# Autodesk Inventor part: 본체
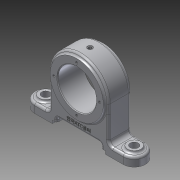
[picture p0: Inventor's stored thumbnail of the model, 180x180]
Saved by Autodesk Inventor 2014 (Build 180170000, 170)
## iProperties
Created: 2019-05
Part Number: 본체
Material: Aluminum 6061
Document SubType Name: Modeling
Designer: kh
Density: 2.71 g/cm^3
Appearance: Aluminum - Flat
Mass: 456.566 g
Surface Area: 322 cm^2
Volume: 168.474 cm^3
Author: kh
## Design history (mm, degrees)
sketch "Sketch1"
  geometry: L1 (-60, 0)-(60, 0); L2 (-60, 15)-(60, 15); L3 (60, -15)-(-60, -15); A1 r 15 centre (-60, 0) between (-60, 15) and (-60, -15); A2 r 15 centre (60, 0) between (60, -15) and (60, 15); 2 further points
  constraints: 8 end point, 4 point on circle, 4 tangent, 2 centre point, 1 coincident, 1 horizontal, 1 midpoint, 1 parallel
  dimensions: "d0" = 120 distance of L1.start L1.end; "d1" = 15 radius of A2
extrude "Extrusion1" new body sketch "Sketch1" distance "d2" = 12; taper "d3" = 0 deg
sketch "Sketch2"
  geometry: L1 (120, 0)-(0, 0) reference; L2 (120, 0)-(120, 12) reference; L3 (0, 12)-(120, 12) reference; L4 (0, 0)-(0, 12) reference; L5 (0, 0)-(0, 0) reference; L6 (0, 0)-(0, 12) reference; L7 (0, 12)-(0, 12) reference; L8 (0, 0)-(0, 12) reference; L9 (120, 0)-(120, 0) reference; L10 (120, 0)-(120, 12) reference; L11 (120, 12)-(120, 12) reference; L12 (120, 0)-(120, 12) reference; L13 (-15, 0)-(-15, 12) reference; L14 (135, 0)-(135, 12) reference; L15 (24, 4)-(96, 4); L16 (96, 4)-(96, 0); L17 (96, 0)-(24, 0); L18 (24, 0)-(24, 4); 2 further points
  constraints: 8 end point, 2 midpoint, 2 parallel, 1 horizontal, 1 perpendicular
  dimensions: "d4" = 72 distance of L16.end L17.end; "d5" = 4 distance of L15.end L16.end
extrude "Extrusion2" cut sketch "Sketch2" stored distance "d6" = 12; taper "d7" = 0 deg
sketch "Sketch3"
  geometry: L1 (96, -8)-(96, -12) reference; L2 (120, -12)-(96, -12) reference; L3 (120, -12)-(120, 0) reference; L4 (0, 0)-(120, 0) reference; L5 (0, -12)-(0, 0) reference; L6 (24, -12)-(0, -12) reference; L7 (24, -12)-(24, -8) reference; L8 (24, -8)-(96, -8) reference; L9 (60, -12)-(60, -8); L10 (30, -2)-(90, -2); L11 (90, -2)-(90, -8); L12 (90, -8)-(30, -8); L13 (30, -8)-(30, -2); L14 (24, -8)-(96, -8) reference; 1 further point
  constraints: 10 end point, 3 midpoint, 2 parallel, 1 horizontal, 1 perpendicular
  dimensions: "d8" = 60 distance of L11.end L12.end; "d9" = 6 distance of L10.end L11.end
extrude "Extrusion3" cut sketch "Sketch3" stored distance "d10" = 12; taper "d11" = 0 deg
sketch "Sketch4"
  geometry: L1 (-15, 0)-(15, 0) reference; L2 (-15, 0)-(-15, 12) reference; L3 (15, 12)-(-15, 12) reference; L4 (15, 0)-(15, 12) reference; L5 (-18, 60)-(-18, 96); L6 (-18, 96)-(18, 96); L7 (18, 96)-(18, 60); L8 (18, 60)-(-18, 60); L9 (-18, 86)-(18, 86); 3 further points
  constraints: 10 end point, 3 parallel, 2 midpoint, 2 perpendicular, 2 point on line, 1 vertical alignment
  dimensions: "d12" = 72 diameter of L6 L8; "d13" = 60 vertical distance of L5.start L1.start; "d14" = 52 diameter of L9 L8; "d15" = 36 distance of L5.end L6.end
revolve "Revolution1" sketch "Sketch4" stored, may be unused: angle "d16" = 90 deg
sketch "Sketch5"
  geometry: L1 (-30, 4)-(-30, 10) reference; L2 (-30, 10)-(30, 10) reference; L3 (30, 10)-(30, 4) reference; L4 (30, 4)-(36, 4) reference; L5 (36, 4)-(36, 0) reference; L6 (60, 0)-(36, 0) reference; L7 (60, 0)-(60, 12) reference; L8 (-60, 12)-(60, 12) reference; L9 (-60, 0)-(-60, 12) reference; L10 (-36, 0)-(-60, 0) reference; L11 (-36, 0)-(-36, 4) reference; L12 (-36, 4)-(-30, 4) reference; L13 (60, 0)-(60, 0) reference; L14 (60, 0)-(60, 12) reference; L15 (60, 12)-(60, 12) reference; L16 (60, 0)-(60, 12) reference; L17 (-60, 0)-(-60, 0) reference; L18 (-60, 0)-(-60, 12) reference; L19 (-60, 12)-(-60, 12) reference; L20 (-60, 0)-(-60, 12) reference; L21 (75, 0)-(75, 12) reference; L22 (-75, 0)-(-75, 12) reference; L23 (40, 60)-(40, 12); L24 (-40, 60)-(-40, 12); L25 (40, 12)-(-40, 12); C1 r 36 at (0, 60) reference; C2 r 26 at (0, 60) reference; A1 r 40 centre (0, 60) between (40, 60) and (-40, 60); 1 further point
  constraints: 6 end point, 2 perpendicular, 2 point on circle, 2 point on line, 2 tangent, 1 centre point, 1 coincident, 1 parallel
  dimensions: "d17" = 80 diameter of A1
extrude "Extrusion4" join sketch "Sketch5" stored distance "d18" = 30; taper "d19" = 0 deg
sketch "Sketch6"
  geometry: L1 (-40, -15)-(-40, 15) reference; L2 (-40, 15)-(-60, 15) reference; L3 (-60, -15)-(-40, -15) reference; L4 (40, 15)-(40, -15) reference; L5 (40, -15)-(60, -15) reference; L6 (60, 15)-(40, 15) reference; C1 r 9 at (-60, 0); C2 r 9 at (60, 0); A1 r 15 centre (-60, 0) between (-60, 15) and (-60, -15) reference; A2 r 15 centre (60, 0) between (60, -15) and (60, 15) reference; 1 further point
  constraints: 2 centre point, 2 coincident
  dimensions: "d20" = 18 diameter of C1; "d21" = 18 diameter of C2
extrude "Extrusion5" join sketch "Sketch6" distance "d22" = 3; taper "d23" = 0 deg
hole "Hole1" diameter "d26" = 11; stored, may be unused: countersink angle "d30" = 90 deg, drill point angle "d32" = 118 deg; dims "d24" = 10, "d25" = 10, "d27" = 6, "d28" = 4, "d29" = 2, "d31" = 8
hole "Hole2" diameter "d35" = 11; stored, may be unused: countersink angle "d39" = 90 deg, drill point angle "d41" = 118 deg; dims "d33" = 10, "d34" = 10, "d36" = 6, "d37" = 4, "d38" = 2, "d40" = 8
workplane "Work Plane1"
sketch "Sketch7"
  geometry: 2 further points
  constraints: 1 coincident
hole "Hole3" sketch "Sketch7" at (0, 0) diameter "d42" = 4.917; stored, may be unused: countersink angle "d46" = 90 deg, drill point angle "d48" = 118 deg; dims "d43" = 8, "d44" = 7, "d45" = 1, "d47" = 10
sketch "Sketch8"
  geometry: C1 r 26 at (0, 0) reference; 1 further point
extrude "Extrusion6" cut sketch "Sketch8" stored distance "d49" = 3; taper "d50" = 0 deg
sketch "Sketch9"
  geometry: C1 r 1 at (0, 0); 1 further point
  constraints: 1 centre point, 1 coincident
  dimensions: "d51" = 2 diameter of C1
extrude "Extrusion7" cut sketch "Sketch9" stored distance "d52" = 3; taper "d53" = 0 deg
sketch "Sketch10"
  geometry: L1 (0, 0)-(0, 31); C1 r 26 at (0, 0) reference; C2 r 36 at (0, 0) reference; 2 further points
  constraints: 2 end point, 1 coincident, 1 vertical
  dimensions: "d54" = 31 distance of L1.start L1.end
hole "Hole4" sketch "Sketch10" at (0, 31), (0, -60), (0, 0) diameter "d55" = 3.242; stored, may be unused: countersink angle "d59" = 90 deg, drill point angle "d61" = 118 deg; dims "d56" = 6, "d57" = 7, "d58" = 1, "d60" = 8
pattern_circular "Circular Pattern1" dims angle "d63" = 360 deg
mirror "Mirror1"
sketch "Sketch11"
  geometry: L1 (-76.592, 19.402)-(-43.408, 19.402); L2 (-43.408, 19.402)-(-43.408, 14.598); L3 (-43.408, 14.598)-(-76.592, 14.598); L4 (-76.592, 14.598)-(-76.592, 19.402); L5 (-76.592, 19.402)-(-43.408, 14.598); L6 (-90, 10)-(-30, 10) reference; 2 further points
  constraints: 2 end point, 1 midpoint, 1 vertical alignment, 2 other
  dimensions: "d65" = 7 distance from line of point (-60, 17) L6
emboss "Emboss1" sketch "Sketch11" dims "d66" = 0.5, "d67" = 0
chamfer "Chamfer1" distance "d68" = 1; stored, may be unused: second distance "d69" = 2, angle "d70" = 45 deg
fillet "Fillet1" dims "d71" = 3
fillet "Fillet3" dims "d73" = 3
workplane "Work Plane2"
sketch "Sketch12"
  geometry: C1 r 1.5 at (0, 86); 2 further points
  constraints: 2 vertical alignment, 1 centre point, 1 other
  dimensions: "d75" = 3 diameter of C1
extrude "Extrusion8" cut sketch "Sketch12" stored distance "d76" = 3; taper "d77" = 0 deg
fillet "Fillet4" dims "d78" = 3
fillet "Fillet5" dims "d79" = 6
fillet "Fillet6" dims "d80" = 3
fillet "Fillet7" dims "d81" = 6
fillet "Fillet8" dims "d82" = 3
fillet "Fillet9" dims "d83" = 3
body "Solid1"
node "Projected Loop1"
node "Projected Loop2"
node "Projected Loop3"
node "Projected Loop4"
node "Projected Loop5"
node "Projected Loop6"
node "Projected Loop7"
node "Projected Loop8"
node "Projected Loop9"
node "Projected Loop10"
node "Projected Loop11"
node "Projected Loop12"
node "Projected Loop13"
other parameters: "d74" = -28.25
